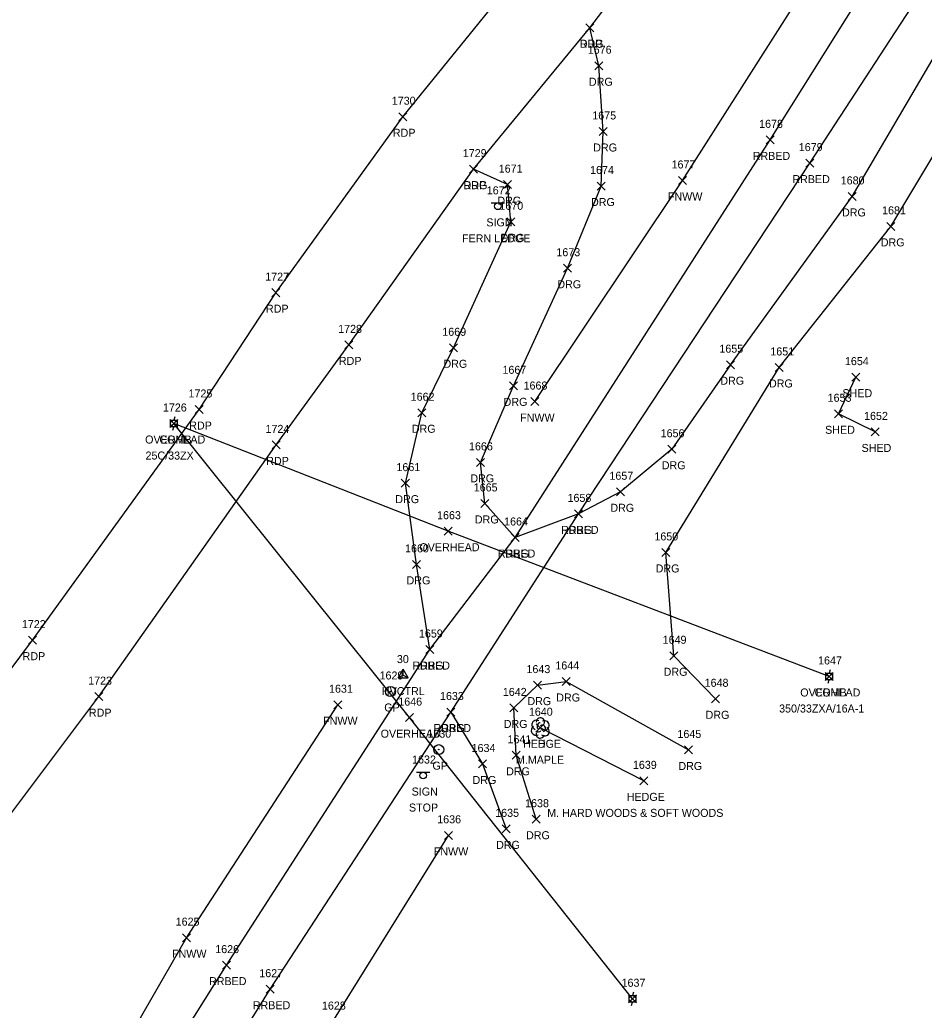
# Model space of a CAD drawing. Extents: x 1508122 to 1515053, y 865012 to 875267.
# Drawn here: x 1511162.4 to 1511388.1, y 869697.2 to 869944.5 of the extents above; entities that cross this region are included whole.
import ezdxf

# ---------------------------------------------------------------- set-up
doc = ezdxf.new("R2010")
doc.units = 0
for name, color, linetype in [('C_A', 7, 'Continuous'), ('C_I', 7, 'Continuous'), ('CPSM', 7, 'Continuous'), ('L_A', 7, 'Continuous'), ('L_C', 7, 'Continuous'), ('L_I', 7, 'Continuous'), ('L_TIC', 7, 'Continuous'), ('LAHR', 7, 'Continuous'), ('LBC', 7, 'Continuous'), ('LFNC', 7, 'Continuous'), ('LTD', 7, 'Continuous'), ('P_A', 7, 'Continuous'), ('P_I', 7, 'Continuous'), ('P_TIC', 7, 'Continuous'), ('PET', 7, 'Continuous'), ('R_A', 7, 'Continuous'), ('R_I', 7, 'Continuous'), ('R_TIC', 7, 'Continuous'), ('RDG', 7, 'Continuous'), ('RGP', 7, 'Continuous'), ('RRB', 7, 'Continuous'), ('S_A', 7, 'Continuous'), ('S_C', 7, 'Continuous'), ('S_I', 7, 'Continuous'), ('SSGN', 7, 'Continuous'), ('U_A', 7, 'Continuous'), ('U_C', 7, 'Continuous'), ('U_I', 7, 'Continuous'), ('U_TIC', 7, 'Continuous'), ('UP', 7, 'Continuous'), ('UT', 7, 'Continuous')]:
    doc.layers.add(name, color=color, linetype=linetype)

msp = doc.modelspace()

# ---------------------------------------------------------------- linework, layer by layer
at = {"layer": 'CPSM'}
for p, q in [((1511256.79, 869780.14), (1511258.04, 869782.31)), ((1511259.29, 869780.14), (1511258.04, 869782.31)), ((1511258.04, 869780.86), (1511258.04, 869782.31)), ((1511256.79, 869780.14), (1511258.04, 869780.86)), ((1511256.79, 869780.14), (1511259.29, 869780.14)), ((1511258.04, 869780.86), (1511258.04, 869780.86)), ((1511258.04, 869780.86), (1511259.29, 869780.14))]:
    msp.add_line(p, q, dxfattribs=at)
at = {"layer": 'L_TIC'}
for points in [[(1511326.8, 869903.4), (1511328.8, 869905.4)], [(1511328.8, 869903.4), (1511326.8, 869905.4)], [(1511370.08, 869854.28), (1511372.08, 869856.28)], [(1511372.08, 869854.28), (1511370.08, 869856.28)], [(1511289.91, 869848.18), (1511291.91, 869850.18)], [(1511291.91, 869848.18), (1511289.91, 869850.18)], [(1511365.76, 869845.13), (1511367.76, 869847.13)], [(1511367.76, 869845.13), (1511365.76, 869847.13)], [(1511374.86, 869840.6), (1511376.86, 869842.6)], [(1511376.86, 869840.6), (1511374.86, 869842.6)], [(1511240.72, 869772.46), (1511242.72, 869774.46)], [(1511242.72, 869772.46), (1511240.72, 869774.46)], [(1511291.27, 869766.71), (1511293.27, 869768.71)], [(1511293.27, 869766.71), (1511291.27, 869768.71)], [(1511317.16, 869753.45), (1511319.16, 869755.45)], [(1511319.16, 869753.45), (1511317.16, 869755.45)], [(1511268.35, 869739.84), (1511270.35, 869741.84)], [(1511270.35, 869739.84), (1511268.35, 869741.84)], [(1511203, 869714.28), (1511205, 869716.28)], [(1511205, 869714.28), (1511203, 869716.28)]]:
    msp.add_lwpolyline(points, dxfattribs=at)
at = {"layer": 'LAHR'}
msp.add_lwpolyline([(1511318.16, 869754.45), (1511292.27, 869767.71)], dxfattribs=at)
at = {"layer": 'LBC'}
msp.add_lwpolyline([(1511375.86, 869841.6), (1511366.76, 869846.13), (1511371.08, 869855.28)], dxfattribs=at)
at = {"layer": 'LFNC'}
for points in [[(1511290.91, 869849.18), (1511327.8, 869904.4), (1511394.98, 870009.98), (1511425.13, 870055.54), (1511455.87, 870105.19), (1511491.53, 870158.85), (1511535.01, 870223.89), (1511575.2, 870287.48), (1511608.77, 870338.28), (1511623.7, 870361.63)], [(1510487.97, 868590.92), (1510484.52, 868592.63), (1510520.32, 868648.34), (1510560.25, 868711.51), (1510582.03, 868746.35), (1510634, 868827.04), (1510686.82, 868909.82), (1510729.04, 868976.39), (1510801.8, 869091.1), (1510852.87, 869170.39), (1510912.76, 869264.38), (1510950.76, 869323.33), (1510992.09, 869387.13), (1511023.8, 869435.93), (1511065.2, 869500.26), (1511113.7, 869573.41), (1511147.07, 869624.31), (1511169.91, 869656.03), (1511204, 869715.28), (1511241.72, 869773.46)], [(1511062.28, 869416.08), (1511104.84, 869482.48), (1511145.99, 869545.07), (1511172.19, 869586.61), (1511203.22, 869634.78), (1511240.52, 869694.32), (1511269.35, 869740.84)]]:
    msp.add_lwpolyline(points, dxfattribs=at)
at = {"layer": 'LTD'}
msp.add_line((1511292.27, 869767.71), (1511292.27, 869767.71), dxfattribs=at)
msp.add_line((1511292.27, 869767.71), (1511292.27, 869767.71), dxfattribs=at)
msp.add_arc((1511292.32, 869769.14), 1.05, 335.5272, 180.9563, dxfattribs=at)
for centre, major_axis, ratio, start_param, end_param in [((1511291.48, 869768.38), (1.21, -0.51), 0.895232, 1.570796, 4.712389), ((1511292.06, 869768.17), (-0.208, -0.792), 0.645439, 3.141593, 6.283185), ((1511293.31, 869768.29), (-1.14, -0.48), 0.949671, 1.570796, 4.712389), ((1511291.19, 869767), (0.58, -1.04), 0.959034, 3.141593, 6.283185), ((1511292.27, 869766.21), (0.26, 1.06), 0.942809, 1.570796, 4.712389), ((1511291.81, 869766.96), (-0.625, -0.083), 0.423636, 0, 3.141593), ((1511292.77, 869767.54), (-0.5, 0.667), 0.989748, 3.141593, 6.283185), ((1511293.27, 869766.88), (-1.09, 0.79), 0.841452, 1.570796, 4.712389)]:
    msp.add_ellipse(centre, major_axis=major_axis, ratio=ratio, start_param=start_param, end_param=end_param, dxfattribs=at)
at = {"layer": 'P_TIC'}
for points in [[(1511303.66, 869941.55), (1511305.66, 869943.55)], [(1511305.66, 869941.55), (1511303.66, 869943.55)], [(1511257, 869919.32), (1511259, 869921.32)], [(1511259, 869919.32), (1511257, 869921.32)], [(1511274.64, 869906.23), (1511276.64, 869908.23)], [(1511276.64, 869906.23), (1511274.64, 869908.23)], [(1511225.31, 869875.38), (1511227.31, 869877.38)], [(1511227.31, 869875.38), (1511225.31, 869877.38)], [(1511243.52, 869862.34), (1511245.52, 869864.34)], [(1511245.52, 869862.34), (1511243.52, 869864.34)], [(1511206.17, 869846.2), (1511208.17, 869848.2)], [(1511208.17, 869846.2), (1511206.17, 869848.2)], [(1511225.38, 869837.36), (1511227.38, 869839.36)], [(1511227.38, 869837.36), (1511225.38, 869839.36)], [(1511164.56, 869788.59), (1511166.56, 869790.59)], [(1511166.56, 869788.59), (1511164.56, 869790.59)], [(1511181.11, 869774.48), (1511183.11, 869776.48)], [(1511183.11, 869774.48), (1511181.11, 869776.48)]]:
    msp.add_lwpolyline(points, dxfattribs=at)
at = {"layer": 'PET'}
for points in [[(1510904.69, 869375.99), (1510944.1, 869457.65), (1510981.65, 869532.24), (1511024.08, 869604.47), (1511042.96, 869631.7), (1511093.88, 869696.57), (1511130.92, 869743.2), (1511165.56, 869789.59), (1511207.17, 869847.2), (1511226.31, 869876.38), (1511258, 869920.32), (1511287.1, 869956.26), (1511314.02, 869991.4), (1511347.57, 870034.24), (1511383.61, 870084.12), (1511412.26, 870126.56)], [(1510922.16, 869361.87), (1510963.34, 869449.46), (1511001.23, 869521.95), (1511042, 869590.98), (1511060.37, 869618.22), (1511110.19, 869682.89), (1511147.27, 869729.24), (1511182.11, 869775.48), (1511226.38, 869838.36), (1511244.52, 869863.34), (1511275.64, 869907.23), (1511304.66, 869942.55), (1511331.68, 869978), (1511364.79, 870019.42), (1511401.8, 870072.69), (1511429.85, 870113.63)]]:
    msp.add_lwpolyline(points, dxfattribs=at)
at = {"layer": 'R_TIC'}
for points in [[(1511303.66, 869941.55), (1511305.66, 869943.55)], [(1511305.66, 869941.55), (1511303.66, 869943.55)], [(1511305.94, 869932.06), (1511307.94, 869934.06)], [(1511307.94, 869932.06), (1511305.94, 869934.06)], [(1511307.01, 869915.64), (1511309.01, 869917.64)], [(1511309.01, 869915.64), (1511307.01, 869917.64)], [(1511348.66, 869913.55), (1511350.66, 869915.55)], [(1511350.66, 869913.55), (1511348.66, 869915.55)], [(1511358.57, 869907.74), (1511360.57, 869909.74)], [(1511360.57, 869907.74), (1511358.57, 869909.74)], [(1511274.64, 869906.23), (1511276.64, 869908.23)], [(1511276.64, 869906.23), (1511274.64, 869908.23)], [(1511283.08, 869902.36), (1511285.08, 869904.36)], [(1511285.08, 869902.36), (1511283.08, 869904.36)], [(1511306.46, 869902.02), (1511308.46, 869904.02)], [(1511308.46, 869902.02), (1511306.46, 869904.02)], [(1511369.12, 869899.42), (1511371.12, 869901.42)], [(1511371.12, 869899.42), (1511369.12, 869901.42)], [(1511283.9, 869893.08), (1511285.9, 869895.08)], [(1511285.9, 869893.08), (1511283.9, 869895.08)], [(1511378.8, 869891.94), (1511380.8, 869893.94)], [(1511380.8, 869891.94), (1511378.8, 869893.94)], [(1511298.05, 869881.48), (1511300.05, 869883.48)], [(1511300.05, 869881.48), (1511298.05, 869883.48)], [(1511269.62, 869861.61), (1511271.62, 869863.61)], [(1511271.62, 869861.61), (1511269.62, 869863.61)], [(1511338.74, 869857.39), (1511340.74, 869859.39)], [(1511340.74, 869857.39), (1511338.74, 869859.39)], [(1511338.74, 869857.39), (1511340.74, 869859.39)], [(1511340.74, 869857.39), (1511338.74, 869859.39)], [(1511350.89, 869856.7), (1511352.89, 869858.7)], [(1511352.89, 869856.7), (1511350.89, 869858.7)], [(1511284.64, 869852.11), (1511286.64, 869854.11)], [(1511286.64, 869852.11), (1511284.64, 869854.11)], [(1511261.72, 869845.39), (1511263.72, 869847.39)], [(1511263.72, 869845.39), (1511261.72, 869847.39)], [(1511324.13, 869836.27), (1511326.13, 869838.27)], [(1511326.13, 869836.27), (1511324.13, 869838.27)], [(1511276.33, 869833), (1511278.33, 869835)], [(1511278.33, 869833), (1511276.33, 869835)], [(1511257.6, 869827.81), (1511259.6, 869829.81)], [(1511259.6, 869827.81), (1511257.6, 869829.81)], [(1511311.29, 869825.65), (1511313.29, 869827.65)], [(1511313.29, 869825.65), (1511311.29, 869827.65)], [(1511277.46, 869822.74), (1511279.46, 869824.74)], [(1511279.46, 869822.74), (1511277.46, 869824.74)], [(1511300.83, 869820.13), (1511302.83, 869822.13)], [(1511302.83, 869820.13), (1511300.83, 869822.13)], [(1511300.83, 869820.13), (1511302.83, 869822.13)], [(1511302.83, 869820.13), (1511300.83, 869822.13)], [(1511285.05, 869814.23), (1511287.05, 869816.23)], [(1511287.05, 869814.23), (1511285.05, 869816.23)], [(1511285.05, 869814.23), (1511287.05, 869816.23)], [(1511287.05, 869814.23), (1511285.05, 869816.23)], [(1511322.6, 869810.5), (1511324.6, 869812.5)], [(1511324.6, 869810.5), (1511322.6, 869812.5)], [(1511260.41, 869807.52), (1511262.41, 869809.52)], [(1511262.41, 869807.52), (1511260.41, 869809.52)], [(1511263.74, 869786.25), (1511265.74, 869788.25)], [(1511265.74, 869786.25), (1511263.74, 869788.25)], [(1511263.74, 869786.25), (1511265.74, 869788.25)], [(1511265.74, 869786.25), (1511263.74, 869788.25)], [(1511324.59, 869784.69), (1511326.59, 869786.69)], [(1511326.59, 869784.69), (1511324.59, 869786.69)], [(1511290.58, 869777.36), (1511292.58, 869779.36)], [(1511292.58, 869777.36), (1511290.58, 869779.36)], [(1511297.79, 869778.27), (1511299.79, 869780.27)], [(1511299.79, 869778.27), (1511297.79, 869780.27)], [(1511284.68, 869771.66), (1511286.68, 869773.66)], [(1511286.68, 869771.66), (1511284.68, 869773.66)], [(1511335.06, 869773.94), (1511337.06, 869775.94)], [(1511337.06, 869773.94), (1511335.06, 869775.94)], [(1511268.99, 869770.64), (1511270.99, 869772.64)], [(1511270.99, 869770.64), (1511268.99, 869772.64)], [(1511268.99, 869770.64), (1511270.99, 869772.64)], [(1511270.99, 869770.64), (1511268.99, 869772.64)], [(1511285.27, 869759.83), (1511287.27, 869761.83)], [(1511287.27, 869759.83), (1511285.27, 869761.83)], [(1511328.27, 869761.16), (1511330.27, 869763.16)], [(1511330.27, 869761.16), (1511328.27, 869763.16)], [(1511276.88, 869757.66), (1511278.88, 869759.66)], [(1511278.88, 869757.66), (1511276.88, 869759.66)], [(1511290.24, 869743.87), (1511292.24, 869745.87)], [(1511292.24, 869743.87), (1511290.24, 869745.87)], [(1511282.77, 869741.46), (1511284.77, 869743.46)], [(1511284.77, 869741.46), (1511282.77, 869743.46)], [(1511212.93, 869707.42), (1511214.93, 869709.42)], [(1511214.93, 869707.42), (1511212.93, 869709.42)], [(1511223.88, 869701.41), (1511225.88, 869703.41)], [(1511225.88, 869701.41), (1511223.88, 869703.41)]]:
    msp.add_lwpolyline(points, dxfattribs=at)
at = {"layer": 'RDG'}
for points in [[(1511339.74, 869858.39), (1511370.12, 869900.42), (1511391.52, 869936.86), (1511412.47, 869971.61), (1511435.65, 870014.48), (1511452, 870038.57), (1511468.75, 870057.98), (1511491.9, 870067.82), (1511518.42, 870063.53), (1511532.14, 870057.87)], [(1511336.06, 869774.94), (1511325.59, 869785.69), (1511323.6, 869811.5), (1511351.89, 869857.7), (1511379.8, 869892.94), (1511402.49, 869930.75), (1511421.62, 869967.18), (1511444.4, 870008.19), (1511460.03, 870032.44), (1511476.55, 870048.63), (1511493.93, 870053.47), (1511514.89, 870051.4), (1511530.02, 870042.93)], [(1511339.74, 869858.39), (1511325.13, 869837.27), (1511312.29, 869826.65), (1511301.83, 869821.13), (1511286.05, 869815.23), (1511278.46, 869823.74), (1511277.33, 869834), (1511285.64, 869853.11), (1511299.05, 869882.48), (1511307.46, 869903.02), (1511308.01, 869916.64), (1511306.94, 869933.06), (1511304.66, 869942.55)], [(1511264.74, 869787.25), (1511261.41, 869808.52), (1511258.6, 869828.81), (1511262.72, 869846.39), (1511270.62, 869862.61), (1511284.9, 869894.08), (1511284.08, 869903.36), (1511275.64, 869907.23)], [(1511291.24, 869744.87), (1511286.27, 869760.83), (1511285.68, 869772.66), (1511291.58, 869778.36), (1511298.79, 869779.27), (1511329.27, 869762.16)], [(1511269.99, 869771.64), (1511277.88, 869758.66), (1511283.77, 869742.46)]]:
    msp.add_lwpolyline(points, dxfattribs=at)
at = {"layer": 'RGP'}
for p, q in [((1511254.9, 869776.77), (1511254.9, 869776.77)), ((1511266.94, 869762.24), (1511266.94, 869762.24))]:
    msp.add_line(p, q, dxfattribs=at)
for centre, radius in [((1511254.9, 869776.77), 1.25), ((1511254.9, 869776.77), 0.0833), ((1511266.94, 869762.24), 1.25), ((1511266.94, 869762.24), 0.0833)]:
    msp.add_circle(centre, radius, dxfattribs=at)
at = {"layer": 'RRB'}
for points in [[(1510567.62, 868706.56), (1510590.3, 868741.33), (1510641.58, 868821.14), (1510694.12, 868904.03), (1510737.34, 868971.49), (1510810.55, 869083.19), (1510862.56, 869162.99), (1510923.65, 869257.51), (1510962.65, 869316.48), (1511003.03, 869380.52), (1511033.75, 869429.1), (1511076.21, 869490.94), (1511122.4, 869564.68), (1511156.76, 869618.82), (1511179.37, 869653.25), (1511213.93, 869708.42), (1511264.74, 869787.25), (1511286.05, 869815.23), (1511349.66, 869914.55), (1511393.09, 869983.89), (1511436.1, 870048.65), (1511490.68, 870132.35)], [(1510600.6, 868735.49), (1510651.55, 868814.96), (1510704.78, 868897.68), (1510748.11, 868964.85), (1510821.21, 869076.32), (1510873.49, 869156.69), (1510934.14, 869250.38), (1510973.56, 869310.54), (1511014.14, 869373.22), (1511046.88, 869423.36), (1511086.93, 869485.24), (1511132.78, 869556.33), (1511168.28, 869611.72), (1511189.07, 869644.73), (1511224.88, 869702.41), (1511269.99, 869771.64), (1511301.83, 869821.13), (1511359.57, 869908.74), (1511403.78, 869976.54), (1511445.67, 870042.93), (1511499.01, 870126.5)]]:
    msp.add_lwpolyline(points, dxfattribs=at)
at = {"layer": 'SSGN'}
for p, q in [((1511280.04, 869898.79), (1511283.37, 869898.79)), ((1511281.69, 869897.96), (1511281.69, 869897.96)), ((1511261.39, 869756.64), (1511264.72, 869756.64)), ((1511263.04, 869755.8), (1511263.04, 869755.8))]:
    msp.add_line(p, q, dxfattribs=at)
for centre in [(1511281.69, 869897.96), (1511263.04, 869755.8)]:
    msp.add_circle(centre, 0.833, dxfattribs=at)
at = {"layer": 'U_TIC'}
for points in [[(1511199.83, 869842.7), (1511201.83, 869844.7)], [(1511201.83, 869842.7), (1511199.83, 869844.7)], [(1511199.83, 869842.7), (1511201.83, 869844.7)], [(1511201.83, 869842.7), (1511199.83, 869844.7)], [(1511268.31, 869815.8), (1511270.31, 869817.8)], [(1511270.31, 869815.8), (1511268.31, 869817.8)], [(1511363.38, 869779.52), (1511365.38, 869781.52)], [(1511365.38, 869779.52), (1511363.38, 869781.52)], [(1511258.63, 869769.24), (1511260.63, 869771.24)], [(1511260.63, 869769.24), (1511258.63, 869771.24)], [(1511314.32, 869699.02), (1511316.32, 869701.02)], [(1511316.32, 869699.02), (1511314.32, 869701.02)]]:
    msp.add_lwpolyline(points, dxfattribs=at)
at = {"layer": 'UP'}
for p, q in [((1511201.08, 869845.37), (1511200.83, 869844.54)), ((1511199.99, 869842.87), (1511199.99, 869844.54)), ((1511199.99, 869844.54), (1511201.66, 869844.54)), ((1511201.66, 869842.87), (1511199.99, 869842.87)), ((1511200.58, 869842.04), (1511200.83, 869842.87)), ((1511200.83, 869843.7), (1511200.83, 869843.7)), ((1511201.66, 869844.54), (1511201.66, 869842.87)), ((1511363.55, 869779.69), (1511363.55, 869781.36)), ((1511363.55, 869781.36), (1511365.22, 869781.36)), ((1511364.63, 869782.19), (1511364.38, 869781.36)), ((1511365.22, 869781.36), (1511365.22, 869779.69)), ((1511365.22, 869779.69), (1511363.55, 869779.69)), ((1511364.13, 869778.86), (1511364.38, 869779.69)), ((1511364.38, 869780.52), (1511364.38, 869780.52)), ((1511314.49, 869699.18), (1511314.49, 869700.85)), ((1511314.49, 869700.85), (1511316.15, 869700.85)), ((1511315.57, 869701.68), (1511315.32, 869700.85)), ((1511315.32, 869700.02), (1511315.32, 869700.02)), ((1511316.15, 869700.85), (1511316.15, 869699.18)), ((1511316.15, 869699.18), (1511314.49, 869699.18)), ((1511315.07, 869698.35), (1511315.32, 869699.18))]:
    msp.add_line(p, q, dxfattribs=at)
for centre in [(1511200.83, 869843.7), (1511364.38, 869780.52), (1511315.32, 869700.02)]:
    msp.add_circle(centre, 0.833, dxfattribs=at)
at = {"layer": 'UT'}
for points in [[(1511315.32, 869700.02), (1511259.63, 869770.24), (1511200.83, 869843.7)], [(1511364.38, 869780.52), (1511269.31, 869816.8), (1511200.83, 869843.7)]]:
    msp.add_lwpolyline(points, dxfattribs=at)

# ---------------------------------------------------------------- texts
at = {"layer": 'C_A'}
msp.add_text('HVCTRL', height=2, dxfattribs=at).set_placement((1511252.74, 869775.86))
at = {"layer": 'C_I'}
msp.add_text('30', height=2, dxfattribs=at).set_placement((1511256.49, 869783.86))
at = {"layer": 'L_A'}
for s, p in [('FNWW', (1511324.15, 869899.4)), ('SHED', (1511367.72, 869850.28)), ('FNWW', (1511287.25, 869844.18)), ('SHED', (1511363.4, 869841.13)), ('SHED', (1511372.5, 869836.6)), ('FNWW', (1511238.07, 869768.46)), ('HEDGE', (1511287.97, 869762.71)), ('H', (1511291.7, 869762.71)), ('HEDGE', (1511313.86, 869749.45)), ('FNWW', (1511265.7, 869735.84)), ('FNWW', (1511200.35, 869710.28))]:
    msp.add_text(s, height=2, dxfattribs=at).set_placement(p)
at = {"layer": 'L_C'}
for s, p in [('M.MAPLE', (1511286.21, 869758.71)), ('M. HARD WOODS & SOFT WOODS', (1511294.02, 869745.45))]:
    msp.add_text(s, height=2, dxfattribs=at).set_placement(p)
at = {"layer": 'L_I'}
for s, p in [('1677', (1511325.06, 869907.4)), ('1654', (1511368.34, 869858.28)), ('1668', (1511288.12, 869852.18)), ('1653', (1511364.02, 869849.13)), ('1652', (1511373.12, 869844.6)), ('1631', (1511239.55, 869776.46)), ('1640', (1511289.44, 869770.71)), ('1640', (1511289.44, 869770.71)), ('1639', (1511315.41, 869757.45)), ('1636', (1511266.56, 869743.84)), ('1625', (1511201.26, 869718.28)), ('1628', (1511237.78, 869697.32))]:
    msp.add_text(s, height=2, dxfattribs=at).set_placement(p)
at = {"layer": 'P_A'}
for p in [(1511302.14, 869937.55), (1511255.48, 869915.32), (1511273.13, 869902.23), (1511223.8, 869871.38), (1511242.01, 869858.34), (1511204.65, 869842.2), (1511223.87, 869833.36), (1511163.05, 869784.59), (1511179.6, 869770.48)]:
    msp.add_text('RDP', height=2, dxfattribs=at).set_placement(p)
at = {"layer": 'P_I'}
for s, p in [('1730', (1511255.22, 869923.32)), ('1729', (1511272.94, 869910.23)), ('1727', (1511223.62, 869879.38)), ('1728', (1511241.83, 869866.34)), ('1725', (1511204.47, 869850.2)), ('1724', (1511223.69, 869841.36)), ('1722', (1511162.87, 869792.59)), ('1723', (1511179.42, 869778.48))]:
    msp.add_text(s, height=2, dxfattribs=at).set_placement(p)
at = {"layer": 'R_A'}
for s, p in [('DRG', (1511302.14, 869937.55)), ('DRG', (1511304.43, 869928.06)), ('DRG', (1511305.5, 869911.64)), ('RRBED', (1511345.31, 869909.55)), ('RRBED', (1511355.21, 869903.74)), ('DRG', (1511273.13, 869902.23)), ('DRG', (1511281.57, 869898.36)), ('DRG', (1511304.95, 869898.02)), ('DRG', (1511367.61, 869895.42)), ('DRG', (1511282.39, 869889.08)), ('DRG', (1511377.29, 869887.94)), ('DRG', (1511296.54, 869877.48)), ('DRG', (1511268.11, 869857.61)), ('DRG', (1511337.23, 869853.39)), ('DRG', (1511337.23, 869853.39)), ('DRG', (1511349.38, 869852.7)), ('DRG', (1511283.13, 869848.11)), ('DRG', (1511260.21, 869841.39)), ('DRG', (1511322.62, 869832.27)), ('DRG', (1511274.82, 869829)), ('DRG', (1511256.09, 869823.81)), ('DRG', (1511309.78, 869821.65)), ('DRG', (1511275.95, 869818.74)), ('RRBED', (1511297.48, 869816.13)), ('DRG', (1511299.32, 869816.13)), ('RRBED', (1511281.69, 869810.23)), ('DRG', (1511283.53, 869810.23)), ('DRG', (1511321.09, 869806.5)), ('DRG', (1511258.9, 869803.52)), ('RRBED', (1511260.39, 869782.25)), ('DRG', (1511262.23, 869782.25)), ('DRG', (1511323.08, 869780.69)), ('DRG', (1511296.27, 869774.27)), ('GP', (1511253.34, 869771.77)), ('DRG', (1511289.07, 869773.36)), ('DRG', (1511333.55, 869769.94)), ('RRBED', (1511265.64, 869766.64)), ('DRG', (1511267.48, 869766.64)), ('DRG', (1511283.16, 869767.66)), ('GP', (1511265.37, 869757.24)), ('DRG', (1511326.76, 869757.16)), ('DRG', (1511283.76, 869755.83)), ('DRG', (1511275.37, 869753.66)), ('DRG', (1511288.73, 869739.87)), ('DRG', (1511281.26, 869737.46)), ('RRBED', (1511209.58, 869703.42)), ('RRBED', (1511220.52, 869697.41))]:
    msp.add_text(s, height=2, dxfattribs=at).set_placement(p)
at = {"layer": 'R_I'}
for s, p in [('1676', (1511304.14, 869936.06)), ('1675', (1511305.27, 869919.64)), ('1678', (1511346.92, 869917.55)), ('1729', (1511272.94, 869910.23)), ('1679', (1511356.82, 869911.74)), ('1671', (1511281.91, 869906.36)), ('1674', (1511304.72, 869906.02)), ('1680', (1511367.29, 869903.42)), ('1670', (1511282.08, 869897.08)), ('1681', (1511377.62, 869895.94)), ('1673', (1511296.31, 869885.48)), ('1669', (1511267.83, 869865.61)), ('1655', (1511337, 869861.39)), ('1655', (1511337, 869861.39)), ('1651', (1511349.72, 869860.7)), ('1667', (1511282.85, 869856.11)), ('1662', (1511259.93, 869849.39)), ('1656', (1511322.34, 869840.27)), ('1666', (1511274.49, 869837)), ('1661', (1511256.38, 869831.81)), ('1657', (1511309.55, 869829.65)), ('1665', (1511275.68, 869826.74)), ('1658', (1511299.09, 869824.13)), ('1658', (1511299.09, 869824.13)), ('1664', (1511283.26, 869818.23)), ('1664', (1511283.26, 869818.23)), ('1650', (1511320.78, 869814.5)), ('1660', (1511258.53, 869811.52)), ('1659', (1511262, 869790.25)), ('1659', (1511262, 869790.25)), ('1649', (1511322.84, 869788.69)), ('1644', (1511296.05, 869782.27)), ('1629', (1511252.16, 869779.77)), ('1643', (1511288.84, 869781.36)), ('1648', (1511333.32, 869777.94)), ('1633', (1511267.25, 869774.64)), ('1633', (1511267.25, 869774.64)), ('1642', (1511282.94, 869775.66)), ('1630', (1511264.11, 869765.24)), ('1645', (1511326.53, 869765.16)), ('1634', (1511275.14, 869761.66)), ('1641', (1511284.1, 869763.83)), ('1638', (1511288.5, 869747.87)), ('1635', (1511281.03, 869745.46)), ('1626', (1511211.14, 869711.42)), ('1627', (1511222.14, 869705.41))]:
    msp.add_text(s, height=2, dxfattribs=at).set_placement(p)
at = {"layer": 'S_A'}
for p in [(1511278.83, 869892.94), (1511260.17, 869750.78)]:
    msp.add_text('SIGN', height=2, dxfattribs=at).set_placement(p)
at = {"layer": 'S_C'}
for s, p in [('FERN LEDGE', (1511272.74, 869888.94)), ('STOP', (1511259.5, 869746.78))]:
    msp.add_text(s, height=2, dxfattribs=at).set_placement(p)
at = {"layer": 'S_I'}
for s, p in [('1672', (1511278.93, 869900.94)), ('1632', (1511260.28, 869758.78))]:
    msp.add_text(s, height=2, dxfattribs=at).set_placement(p)
at = {"layer": 'U_A'}
for s, p in [('OVERHEAD', (1511193.64, 869838.7)), ('OVERHEAD', (1511193.64, 869838.7)), ('COMB', (1511197.21, 869838.7)), ('OVERHEAD', (1511262.12, 869811.8)), ('OVERHEAD', (1511357.19, 869775.52)), ('COMB', (1511360.77, 869775.52)), ('OVERHEAD', (1511252.44, 869765.24))]:
    msp.add_text(s, height=2, dxfattribs=at).set_placement(p)
at = {"layer": 'U_C'}
for s, p in [('25C/33ZX', (1511193.74, 869834.7)), ('350/33ZXA/16A-1', (1511351.91, 869771.52))]:
    msp.add_text(s, height=2, dxfattribs=at).set_placement(p)
at = {"layer": 'U_I'}
for s, p in [('1726', (1511198.08, 869846.7)), ('1726', (1511198.08, 869846.7)), ('1726', (1511198.08, 869846.7)), ('1663', (1511266.52, 869819.8)), ('1647', (1511361.64, 869783.52)), ('1647', (1511361.64, 869783.52)), ('1646', (1511256.84, 869773.24)), ('1637', (1511312.58, 869703.02)), ('1637', (1511312.58, 869703.02))]:
    msp.add_text(s, height=2, dxfattribs=at).set_placement(p)

doc.saveas('drawing.dxf')
